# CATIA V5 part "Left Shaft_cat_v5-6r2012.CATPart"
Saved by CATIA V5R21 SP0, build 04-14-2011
Part number: Left hand shaft
Bounding box of the stored display mesh (mm): x 0 to 100, y -25 to 25, z -35 to 35
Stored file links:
  D:\CATIA V5R21 E-RESOURCES\CATIA-V5R21\catia-v5r21-Tut\c16-catia-v5r21-tut\c16-catia-v5r21-tut02\Left Shaft_cat_v5r21.CATPart
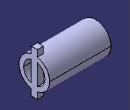
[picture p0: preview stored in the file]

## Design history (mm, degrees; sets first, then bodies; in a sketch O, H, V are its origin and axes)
Body1 (main body)
  Sketch1 on yz-plane, origin (0, 0, 0), H (0, 1, 0), V (0, 0, 1)
    circle A1 centre (0, 0) radius 25
    circle A2 centre (0, 0) radius 17.5
    radius A1 = 25
    radius A2 = 17.5
  Pad1: profile Sketch1, direction (1, 0, 0), length 100
  Sketch2 on end face of Pad1, origin (100, 0, 0), H (0, 1, 0), V (0, 0, 1)
    line L1 (5, 35) -> (5, -35)
    line L2 (5, -35) -> (-5, -35)
    line L3 (-5, -35) -> (-5, 35)
    line L4 (-5, 35) -> (5, 35)
    length L1 = 70
    length L4 = 10
    vertical: L1 V, L3 V
    horizontal: L2 H, L4 H
    equidistance: L1 L3 O, L2 L4 O
  Pad2: profile Sketch2, direction (-1, 0, 0), length 10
